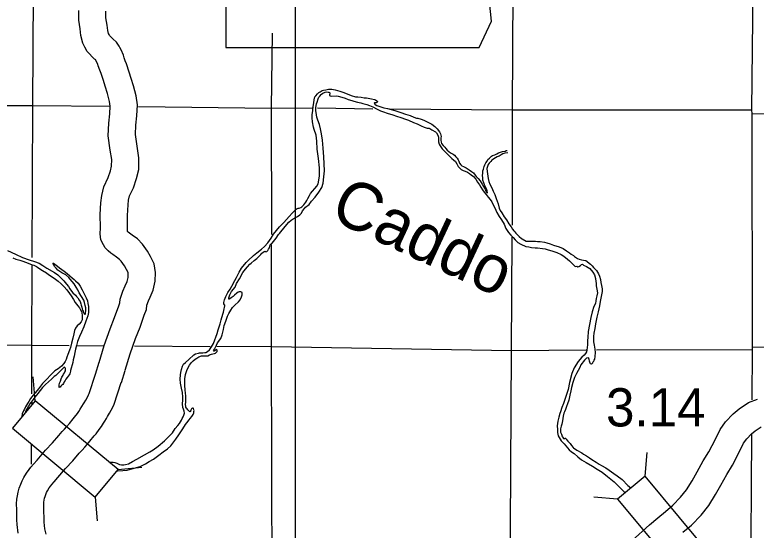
# Model space of a CAD drawing. Extents: x 369523 to 838377, y 495025 to 936819.
# Drawn here: x 464249 to 480625, y 835032 to 846414 of the extents above; entities that cross this region are included whole.
import ezdxf

# ---------------------------------------------------------------- set-up
doc = ezdxf.new("R2010")
doc.units = 0
for name, color, linetype in [('21', 7, 'Continuous'), ('22', 7, 'Continuous'), ('DSN_DRFT_Junk-No-Plot', 7, 'Continuous'), ('Level 1', 7, 'Continuous'), ('Level 10', 7, 'Continuous'), ('Level 15', 7, 'Continuous'), ('Level 21', 7, 'Continuous'), ('Level 22', 7, 'Continuous')]:
    doc.layers.add(name, color=color, linetype=linetype)

msp = doc.modelspace()

# ---------------------------------------------------------------- linework, layer by layer
at = {"layer": '21'}
msp.add_line((470439, 932859), (470439, 762579), dxfattribs=at)
at = {"layer": '22'}
msp.add_lwpolyline([(467669, 854041), (468069, 851377), (467891, 847336), (468247, 847113), (468913, 847113), (468913, 845692), (474508, 845692), (474775, 846270), (474686, 847202), (474819, 848268), (475308, 849112), (475619, 849734), (476063, 850400), (476329, 851110), (476551, 851688), (476951, 852176), (477040, 852487), (476862, 852709), (475485, 852709), (475796, 853331), (475841, 853730), (475656, 854037)], close=True, dxfattribs=at)
at = {"layer": 'Level 1'}
for points in [[(465847, 845607), (465797, 845701), (465754, 845785), (465708, 845958), (465694, 846105), (465662, 846297), (465661, 846512)], [(466340, 845959), (466330, 845977), (466318, 846001), (466300, 846065), (466289, 846183), (466262, 846347), (466261, 846497)], [(466689, 838567), (466793, 838924), (466914, 839264), (467016, 839518), (467108, 839779), (467156, 839906), (467167, 840002), (467198, 840095), (467236, 840179), (467305, 840334), (467350, 840530), (467357, 840724), (467328, 840912), (467245, 841075), (467176, 841194), (467068, 841352), (466962, 841465), (466844, 841550), (466755, 841616), (466737, 841627), (466738, 841708), (466737, 841985), (466750, 842215), (466760, 842319), (466784, 842418), (466867, 842596), (466938, 842796), (466986, 842995), (466988, 843258), (466952, 843514), (466912, 843771), (466925, 843974), (466946, 844180), (466957, 844426), (466927, 844622), (466870, 844843), (466818, 845010), (466777, 845149), (466715, 845328), (466685, 845400), (466663, 845465), (466647, 845523), (466595, 845644), (466567, 845693), (466554, 845720), (466493, 845811), (466413, 845884), (466403, 845891), (466340, 845959)], [(466113, 838734), (466222, 839109), (466353, 839476), (466454, 839730), (466544, 839986), (466569, 840050), (466579, 840131), (466638, 840313), (466689, 840425), (466733, 840526), (466753, 840610), (466756, 840688), (466750, 840725), (466718, 840787), (466668, 840873), (466598, 840976), (466564, 841012), (466491, 841065), (466417, 841120), (466369, 841149), (466308, 841199), (466247, 841265), (466204, 841333), (466152, 841447), (466137, 841578), (466138, 841709), (466137, 842001), (466151, 842260), (466167, 842421), (466216, 842618), (466311, 842823), (466362, 842968), (466387, 843069), (466388, 843218), (466358, 843427), (466309, 843743), (466327, 844024), (466347, 844224), (466355, 844394), (466338, 844502), (466293, 844678), (466244, 844836), (466205, 844966), (466153, 845116), (466124, 845189), (466091, 845285), (466080, 845323), (466056, 845379), (466037, 845413), (466035, 845417), (466006, 845437), (465847, 845607)], [(466033, 838474), (466115, 838739)], [(464295, 835258), (464290, 835501), (464286, 835593), (464286, 835616), (464296, 835720), (464306, 835794), (464321, 835870), (464344, 835961), (464378, 836046), (464409, 836121), (464450, 836196), (464506, 836294), (464567, 836375), (464602, 836420), (464664, 836491), (464739, 836579), (464926, 836800), (465083, 836962), (465219, 837125), (465294, 837210), (465346, 837263), (465388, 837315), (465454, 837389), (465539, 837489), (465568, 837527), (465631, 837610), (465663, 837653), (465691, 837702), (465732, 837767), (465768, 837822), (465782, 837844), (465816, 837905), (465844, 837957), (465877, 838022), (465890, 838048), (466029, 838476)], [(466604, 838290), (466688, 838562)], [(464896, 835249), (464890, 835510), (464886, 835593), (464892, 835651), (464898, 835694), (464906, 835739), (464916, 835775), (464933, 835819), (464951, 835861), (464973, 835902), (465009, 835964), (465044, 836011), (465065, 836038), (465119, 836100), (465197, 836192), (465370, 836397), (465529, 836560), (465673, 836734), (465734, 836802), (465794, 836864), (465844, 836925), (465907, 836995), (466005, 837112), (466044, 837162), (466113, 837252), (466166, 837325), (466205, 837392), (466237, 837443), (466272, 837497), (466299, 837539), (466341, 837614), (466376, 837679), (466412, 837750), (466446, 837816), (466600, 838291)], [(477875, 834799), (478269, 835151), (478449, 835301), (478619, 835444), (478785, 835584), (478956, 835759), (479085, 835923), (479208, 836123), (479320, 836321), (479457, 836567), (479576, 836763), (479724, 837044), (479829, 837255), (479947, 837428), (480116, 837605), (480252, 837711), (480457, 837849), (480657, 837926)], [(479006, 834985), (479194, 835144), (479408, 835363), (479578, 835579), (479725, 835818), (479843, 836027), (479976, 836265), (480099, 836468), (480258, 836771), (480348, 836951), (480415, 837049), (480519, 837159), (480604, 837224), (480736, 837314)], [(464320, 834964), (464300, 835160), (464295, 835258)], [(464941, 834945), (464913, 835064), (464899, 835208), (464896, 835249)]]:
    msp.add_lwpolyline(points, dxfattribs=at)
at = {"layer": 'Level 10'}
for points in [[(468507, 838976), (468551, 839016), (468594, 839080), (468638, 839156), (468719, 839374), (468742, 839456), (468786, 839588), (468809, 839680), (468841, 839800), (468856, 839846), (468874, 839920), (468882, 839950), (468890, 839988), (468886, 840000), (468879, 840012), (468869, 840032), (468869, 840060), (468881, 840122), (468911, 840192), (468954, 840278), (469002, 840358), (469043, 840424), (469105, 840546), (469144, 840610), (469202, 840729), (469259, 840815), (469359, 840947), (469402, 840989), (469520, 841098), (469597, 841160), (469699, 841240), (469763, 841297), (469840, 841377), (469910, 841483), (469965, 841571), (470029, 841649), (470097, 841728), (470188, 841830), (470248, 841896), (470307, 841958), (470377, 842033), (470415, 842073), (470433, 842095), (470461, 842119), (470484, 842137), (470506, 842143), (470528, 842147), (470570, 842159), (470592, 842175), (470632, 842218), (470674, 842276), (470698, 842316), (470719, 842354), (470759, 842422), (470783, 842470), (470922, 842626), (470952, 842680), (470965, 842760), (470977, 842856), (470978, 843036), (470953, 843242), (470930, 843449), (470919, 843621), (470906, 843759), (470863, 843882), (470845, 843930), (470824, 844050), (470816, 844136), (470820, 844203), (470833, 844301), (470839, 844389), (470850, 844471), (470862, 844539), (470878, 844599), (470899, 844627), (470935, 844667), (470965, 844695), (470991, 844716), (471041, 844740), (471067, 844750), (471117, 844756), (471179, 844772), (471253, 844773), (471325, 844759), (471425, 844726), (471513, 844700), (471677, 844633), (471774, 844606), (471822, 844600), (471896, 844594), (471968, 844583), (472020, 844577), (472128, 844556), (472194, 844544), (472216, 844534), (472246, 844514), (472270, 844498), (472262, 844490), (472254, 844484), (472242, 844480), (472232, 844472)], [(469288, 840723), (469345, 840795), (469391, 840847), (469439, 840906), (469469, 840930), (469534, 840986), (469592, 841034), (469648, 841082), (469684, 841118), (469708, 841148), (469727, 841165), (469759, 841185), (469781, 841193), (469791, 841179), (469817, 841189), (469835, 841209), (469855, 841237), (469873, 841267), (469883, 841305), (469889, 841333), (469916, 841361), (469930, 841373), (469960, 841411), (470018, 841482), (470073, 841560), (470093, 841584), (470223, 841736), (470302, 841834), (470354, 841875), (470398, 841905), (470463, 841945), (470495, 841963), (470545, 841999), (470579, 842032), (470605, 842082), (470650, 842140), (470668, 842164), (470748, 842222), (470804, 842300), (470881, 842387), (470961, 842495), (471030, 842601), (471058, 842695), (471073, 842835), (471086, 842969), (471081, 843126), (471072, 843278), (471061, 843472), (471043, 843645), (471022, 843785), (470999, 843897), (470977, 843989), (470940, 844086), (470920, 844152), (470907, 844254), (470901, 844296), (470899, 844366), (470912, 844446), (470926, 844482), (470946, 844558), (470966, 844592), (470987, 844618), (471013, 844652), (471021, 844662), (471053, 844680), (471101, 844704), (471131, 844710), (471169, 844704), (471183, 844705), (471197, 844701), (471205, 844693), (471207, 844677), (471205, 844667), (471201, 844647), (471203, 844633), (471217, 844623), (471241, 844619), (471347, 844623), (471391, 844620), (471470, 844596), (471544, 844571), (471614, 844545), (471696, 844519), (471736, 844506), (471818, 844486), (471894, 844468), (471936, 844457), (471964, 844449), (472027, 844433), (472083, 844412), (472155, 844378), (472255, 844328), (472329, 844293), (472393, 844269), (472470, 844242), (472598, 844204), (472678, 844177), (472776, 844145), (472880, 844110), (472946, 844084), (473057, 844035)], [(472232, 844472), (472218, 844468), (472208, 844470), (472194, 844468), (472186, 844460), (472198, 844444), (472205, 844436), (472247, 844412), (472331, 844383), (472401, 844363), (472479, 844344), (472561, 844324), (472641, 844302), (472709, 844279), (472775, 844259), (472878, 844220), (472978, 844190), (473062, 844155), (473120, 844133), (473152, 844131), (473222, 844110), (473280, 844086), (473375, 844043), (473457, 844001), (473529, 843948), (473575, 843896), (473628, 843828), (473654, 843788), (473666, 843725), (473661, 843699), (473659, 843681), (473659, 843647), (473663, 843603), (473673, 843573), (473707, 843529), (473744, 843493), (473770, 843465), (473802, 843426), (473832, 843398), (473876, 843366), (473928, 843336), (473959, 843313), (473991, 843279), (474019, 843247), (474041, 843211), (474057, 843181), (474074, 843140), (474098, 843098), (474126, 843080), (474156, 843064), (474188, 843050), (474222, 843036), (474244, 843019), (474288, 842993), (474340, 842957), (474379, 842923), (474417, 842870), (474441, 842842), (474481, 842798), (474528, 842744), (474552, 842709), (474570, 842675), (474590, 842645), (474604, 842621), (474622, 842589), (474637, 842565), (474645, 842547), (474649, 842533), (474655, 842521), (474665, 842503), (474671, 842492), (474687, 842486), (474689, 842486), (474683, 842524), (474665, 842569), (474652, 842599), (474626, 842659), (474610, 842701), (474586, 842761), (474583, 842813), (474581, 842868), (474585, 842914), (474590, 842970), (474598, 843006), (474618, 843064), (474634, 843102), (474656, 843142), (474679, 843184), (474697, 843215), (474731, 843249), (474775, 843289), (474799, 843307), (474849, 843323), (474898, 843347), (474934, 843363), (474978, 843378), (475020, 843392), (475078, 843404), (475104, 843414), (475126, 843420)], [(473057, 844035), (473137, 844007), (473223, 843962), (473291, 843934), (473357, 843909), (473381, 843911), (473401, 843911), (473419, 843901), (473460, 843877), (473542, 843830), (473562, 843806), (473596, 843754), (473606, 843714), (473607, 843656), (473609, 843610), (473625, 843559), (473643, 843517), (473692, 843451), (473728, 843415), (473770, 843374), (473819, 843324), (473861, 843284), (473901, 843244), (473941, 843209), (473981, 843177), (474016, 843123), (474044, 843067), (474072, 843032), (474110, 842996), (474150, 842976), (474196, 842958), (474249, 842937), (474289, 842909), (474331, 842881), (474381, 842840), (474433, 842784), (474472, 842716), (474510, 842660), (474542, 842609), (474577, 842545), (474613, 842499), (474661, 842442), (474708, 842384), (474746, 842336), (474782, 842284), (474810, 842235), (474849, 842149), (474899, 842051), (474950, 841962), (474998, 841884), (475057, 841789), (475095, 841693), (475152, 841607), (475206, 841546), (475254, 841496), (475299, 841448), (475363, 841383), (475423, 841345), (475535, 841294), (475601, 841288), (475665, 841278), (475740, 841271), (475794, 841271), (475902, 841252), (475966, 841244), (476030, 841226), (476108, 841205), (476218, 841165), (476314, 841124), (476375, 841086), (476457, 841021), (476499, 840979), (476557, 840919), (476596, 840884), (476628, 840852), (476664, 840860), (476684, 840848), (476710, 840852), (476744, 840874), (476764, 840901), (476788, 840909), (476812, 840887), (476876, 840859), (476950, 840810), (477020, 840732), (477055, 840668), (477077, 840593), (477086, 840525), (477092, 840485), (477092, 840431), (477106, 840353), (477117, 840273), (477105, 840211), (477088, 840151), (477084, 840099), (477078, 840039), (477040, 839973), (477003, 839857), (476974, 839731), (476915, 839420), (476904, 839288)], [(475138, 843365), (475070, 843356), (475031, 843340), (474995, 843322), (474945, 843292), (474905, 843275), (474869, 843253), (474811, 843219), (474789, 843205), (474761, 843177), (474730, 843135), (474708, 843105), (474690, 843065), (474678, 843019), (474683, 842951), (474689, 842905), (474699, 842849), (474705, 842797), (474720, 842731), (474744, 842676), (474782, 842590), (474813, 842522), (474849, 842446), (474880, 842359), (474928, 842239), (474951, 842143), (474973, 842092), (475007, 842040), (475060, 841954), (475108, 841885), (475163, 841799), (475209, 841733), (475245, 841682), (475271, 841644), (475290, 841624), (475316, 841592), (475354, 841552), (475392, 841517), (475442, 841475), (475458, 841463), (475491, 841445), (475509, 841435), (475545, 841418), (475577, 841418), (475623, 841416), (475667, 841418), (475697, 841416), (475747, 841413), (475793, 841409), (475851, 841405), (475951, 841390), (475997, 841380), (476077, 841356), (476149, 841329), (476275, 841289), (476358, 841250), (476438, 841204), (476504, 841157), (476540, 841131), (476590, 841101), (476615, 841079), (476681, 841034), (476715, 841014), (476767, 841002), (476807, 840997), (476861, 840989), (476962, 840909), (477000, 840870), (477034, 840832), (477098, 840766), (477145, 840695), (477165, 840639), (477187, 840567), (477196, 840499), (477210, 840439), (477222, 840360), (477223, 840306), (477182, 840084), (477162, 839988), (477135, 839854), (477104, 839740), (477076, 839592), (477057, 839488), (477040, 839384), (477030, 839310), (477033, 839194), (477047, 839115), (477063, 839027), (477066, 838957), (477058, 838867), (477051, 838809), (477039, 838785), (477029, 838759), (477019, 838739), (477011, 838725), (477007, 838717), (476997, 838705), (476985, 838695), (476965, 838707), (476959, 838723), (476953, 838739)], [(464087, 841206), (464263, 841129), (464416, 841056), (464562, 841005), (464686, 840967), (464788, 840926), (464867, 840880), (464953, 840819), (465125, 840720), (465202, 840668), (465264, 840607), (465332, 840537), (465393, 840464), (465435, 840412), (465467, 840364), (465500, 840307), (465532, 840271), (465586, 840221), (465612, 840195), (465642, 840161), (465671, 840114), (465689, 840082), (465707, 840032), (465717, 840000), (465727, 839956), (465738, 839918), (465746, 839892), (465756, 839870), (465762, 839853), (465776, 839825), (465780, 839809), (465794, 839797), (465802, 839801), (465812, 839811), (465812, 839825), (465816, 839893), (465816, 839941), (465805, 839995), (465791, 840060), (465771, 840114), (465724, 840196)], [(464208, 841045), (464274, 841021), (464358, 840996), (464428, 840972), (464542, 840929), (464632, 840895), (464670, 840883), (464729, 840856), (464753, 840840), (464799, 840802), (464863, 840769), (464945, 840719), (464992, 840681), (465070, 840630), (465150, 840576), (465204, 840531), (465273, 840473), (465341, 840406), (465399, 840338), (465458, 840258), (465494, 840205), (465543, 840127), (465581, 840063), (465639, 839984), (465676, 839940), (465692, 839914), (465720, 839864), (465726, 839834)], [(465724, 840196), (465672, 840275), (465641, 840337), (465603, 840399), (465557, 840473), (465518, 840526), (465472, 840574), (465442, 840610), (465374, 840671), (465285, 840717), (465199, 840772), (465161, 840816), (465127, 840856), (465104, 840904), (465090, 840930), (465104, 840930), (465195, 840860), (465233, 840826), (465339, 840753), (465402, 840701), (465464, 840648), (465518, 840602), (465556, 840568), (465588, 840539), (465645, 840487), (465691, 840423), (465737, 840338), (465782, 840252), (465828, 840166), (465855, 840097), (465865, 840037), (465875, 839975), (465878, 839905), (465876, 839837), (465858, 839763), (465815, 839651), (465772, 839525), (465720, 839405), (465675, 839309), (465635, 839197), (465612, 839107), (465588, 839027), (465573, 838957), (465563, 838873), (465540, 838793), (465528, 838737), (465479, 838559), (465471, 838501), (465465, 838483), (465451, 838463), (465429, 838433), (465402, 838405), (465374, 838365), (465364, 838339), (465342, 838307), (465322, 838275), (465306, 838249), (465285, 838231), (465265, 838211), (465247, 838194), (465241, 838188), (465231, 838186), (465227, 838200), (465228, 838236), (465238, 838278), (465254, 838326), (465272, 838372), (465290, 838408), (465315, 838452), (465327, 838476), (465347, 838510), (465357, 838527), (465367, 838549), (465371, 838577), (465369, 838592), (465367, 838604), (465360, 838620), (465346, 838634), (465332, 838628), (465291, 838586), (465257, 838552), (465201, 838494), (465155, 838450), (465121, 838423), (465062, 838367), (464994, 838311), (464926, 838249), (464863, 838185), (464809, 838114), (464759, 838048), (464694, 837970), (464652, 837918), (464610, 837860), (464579, 837820), (464549, 837772), (464497, 837685), (464483, 837653), (464474, 837614)], [(468204, 837622), (468206, 837654), (468208, 837674), (468204, 837688), (468197, 837716), (468187, 837728), (468175, 837726), (468161, 837718), (468152, 837710), (468140, 837682), (468132, 837660), (468126, 837650), (468112, 837648), (468100, 837658), (468094, 837666), (468070, 837690), (468052, 837711), (468039, 837729), (468029, 837751), (468023, 837769), (468021, 837805), (468027, 837857), (468028, 837945), (468024, 838013), (468022, 838043), (468013, 838147), (468005, 838214), (468002, 838300), (468004, 838376), (468018, 838470), (468047, 838560), (468073, 838612), (468110, 838678), (468152, 838738), (468190, 838774), (468236, 838811), (468266, 838833), (468311, 838857), (468375, 838881), (468425, 838881), (468511, 838886), (468551, 838904), (468593, 838916), (468623, 838924), (468657, 838935), (468681, 838945), (468703, 838961), (468717, 838979), (468719, 838993), (468715, 839005), (468709, 839017), (468701, 839021), (468683, 839009), (468675, 839003), (468665, 838995), (468659, 838990), (468655, 838986), (468647, 838982), (468639, 838990), (468639, 838994), (468663, 839026), (468704, 839117), (468728, 839167), (468797, 839263), (468829, 839349), (468853, 839435), (468858, 839467), (468876, 839553), (468907, 839647), (468949, 839755), (468977, 839815), (469022, 839891), (469058, 839953), (469112, 840003), (469189, 840076), (469227, 840120), (469257, 840186), (469268, 840230), (469274, 840262), (469268, 840282), (469258, 840292), (469244, 840299), (469224, 840299), (469204, 840295), (469182, 840285), (469150, 840265), (469104, 840225), (469069, 840193), (469029, 840167), (468999, 840142), (468997, 840140), (468983, 840134), (468979, 840134), (468977, 840140), (468979, 840160), (469000, 840232), (469036, 840302), (469113, 840401), (469149, 840477), (469208, 840583), (469288, 840723)], [(465726, 839834), (465738, 839773), (465737, 839729), (465735, 839681), (465713, 839633), (465671, 839584), (465626, 839548), (465588, 839496), (465568, 839444), (465551, 839366), (465533, 839276), (465502, 839164), (465480, 839066), (465454, 839008), (465417, 838912), (465399, 838850), (465380, 838798), (465362, 838760), (465328, 838714), (465278, 838652), (465205, 838594), (465135, 838549), (465053, 838471), (464938, 838355), (464860, 838268), (464771, 838156), (464707, 838076), (464656, 838012), (464598, 837940), (464558, 837875), (464527, 837829), (464483, 837753), (464459, 837701), (464439, 837667), (464414, 837599), (464404, 837541)], [(476904, 839288), (476902, 839218), (476897, 839126), (476884, 839010), (476874, 838970), (476852, 838932), (476828, 838900), (476772, 838854), (476693, 838759), (476602, 838617), (476550, 838491), (476499, 838291), (476468, 838139), (476439, 838053), (476409, 837941), (476366, 837827), (476334, 837743), (476301, 837645), (476289, 837607), (476265, 837529), (476240, 837441), (476232, 837339), (476233, 837257), (476237, 837186), (476249, 837118), (476292, 837040), (476316, 837006), (476358, 836962), (476384, 836937), (476419, 836893), (476457, 836847), (476495, 836805), (476547, 836764), (476604, 836722), (476682, 836651), (476764, 836587), (476867, 836524), (477009, 836443), (477111, 836383), (477226, 836310), (477338, 836215), (477487, 836097), (477616, 835978), (477728, 835855)], [(466343, 836528), (466362, 836531), (466422, 836531), (466456, 836525), (466502, 836509), (466530, 836496), (466562, 836486), (466604, 836476), (466658, 836472), (466694, 836480), (466762, 836497), (466850, 836547), (466943, 836599), (467111, 836694), (467228, 836761), (467308, 836809), (467418, 836891), (467555, 837008), (467635, 837088), (467728, 837183), (467792, 837275), (467851, 837341), (467885, 837389), (467929, 837465), (467943, 837495), (467966, 837533), (467982, 837571), (467996, 837619), (467992, 837659), (467974, 837705), (467961, 837741), (467951, 837819), (467958, 837905), (467958, 837971), (467950, 838072), (467927, 838170), (467909, 838276), (467904, 838368), (467908, 838460), (467917, 838515), (467931, 838579), (467955, 838651), (467974, 838697), (468020, 838738), (468096, 838800), (468201, 838908), (468237, 838928), (468303, 838943), (468327, 838947), (468355, 838951), (468399, 838951), (468445, 838955), (468465, 838958), (468507, 838976)], [(476953, 838739), (476945, 838767), (476935, 838807), (476929, 838819), (476928, 838832), (476920, 838838), (476880, 838832), (476872, 838826), (476831, 838790), (476753, 838682), (476726, 838622), (476654, 838490), (476613, 838404), (476577, 838290), (476546, 838180), (476528, 838106), (476505, 838012), (476483, 837906), (476460, 837826), (476434, 837764), (476410, 837700), (476389, 837644), (476377, 837614), (476359, 837548), (476344, 837448), (476330, 837376), (476314, 837328), (476303, 837270), (476301, 837224), (476303, 837196), (476323, 837152), (476329, 837134), (476335, 837118), (476348, 837092), (476356, 837078), (476370, 837060), (476392, 837054), (476396, 837055), (476404, 837063), (476410, 837065), (476420, 837057), (476430, 837045), (476462, 837001), (476516, 836949), (476547, 836902), (476583, 836858), (476587, 836850), (476665, 836798), (476773, 836739), (476814, 836709), (476874, 836672), (476944, 836628), (476998, 836592), (477091, 836533), (477157, 836491), (477211, 836462), (477305, 836406), (477376, 836355), (477478, 836285), (477556, 836230), (477663, 836150), (477791, 836021), (477855, 835965)], [(466502, 836345), (466523, 836344), (466635, 836348), (466728, 836359), (466830, 836387), (467020, 836438), (467136, 836497), (467218, 836547), (467311, 836597), (467429, 836692), (467528, 836762), (467624, 836827), (467694, 836897), (467759, 836983), (467807, 837045), (467871, 837139), (467898, 837185), (467958, 837268), (468021, 837366), (468047, 837404), (468097, 837472), (468119, 837502), (468158, 837544), (468190, 837586), (468204, 837622)]]:
    msp.add_lwpolyline(points, dxfattribs=at)
at = {"layer": 'Level 15'}
for points in [[(480533, 837907), (480540, 839014), (480544, 839074), (480534, 844230), (480532, 844312), (480584, 849668), (480587, 849734), (480600, 854966)], [(480504, 833688), (480527, 837143)]]:
    msp.add_lwpolyline(points, dxfattribs=at)
at = {"layer": 'Level 21'}
for p, q in [((464701, 837892), (464653, 838417)), ((478169, 836224), (478217, 836749)), ((466528, 836373), (467054, 836421)), ((466022, 835764), (466070, 835238)), ((477560, 835717), (477035, 835764))]:
    msp.add_line(p, q, dxfattribs=at)
for points in [[(466528, 836373), (464701, 837892), (464195, 837283), (466022, 835764)], [(477560, 835717), (479082, 833891), (479690, 834398), (478169, 836224)]]:
    msp.add_lwpolyline(points, close=True, dxfattribs=at)
at = {"layer": 'Level 22'}
for points in [[(475239, 841765), (475243, 844312), (475270, 849584), (475291, 854943)], [(464634, 841057), (464648, 844414), (464660, 846897)], [(469923, 841559), (469921, 844353), (469940, 846008)], [(459296, 844413), (464648, 844414), (466345, 844394)], [(466982, 844387), (469921, 844353), (470819, 844361)], [(470933, 844362), (472155, 844340)], [(472529, 844334), (475243, 844312), (480532, 844312)], [(480534, 844230), (482954, 844232)], [(475191, 833779), (475217, 838994), (475232, 841506)], [(469935, 832833), (469936, 833807), (469918, 839079), (469921, 841343)], [(464623, 838046), (464624, 839114), (464633, 840879)], [(465446, 839102), (464624, 839114), (459945, 839154)], [(466197, 839099), (465618, 839103)], [(468562, 839080), (466890, 839093)], [(476868, 839008), (475217, 838994), (469918, 839079), (468710, 839089)], [(480540, 839014), (477096, 839005)], [(485917, 838938), (485887, 838938), (480544, 839074)], [(464629, 837814), (464630, 837856)], [(464620, 836488), (464620, 836931)]]:
    msp.add_lwpolyline(points, dxfattribs=at)

# ---------------------------------------------------------------- texts
at = {"layer": 'DSN_DRFT_Junk-No-Plot'}
msp.add_text('3.14', height=844.8, dxfattribs=at).set_placement((477308, 837323))
at = {"layer": 'Level 10'}
msp.add_text('Caddo', height=1056, rotation=335, dxfattribs=at).set_placement((471167, 841923))

doc.saveas('drawing.dxf')
